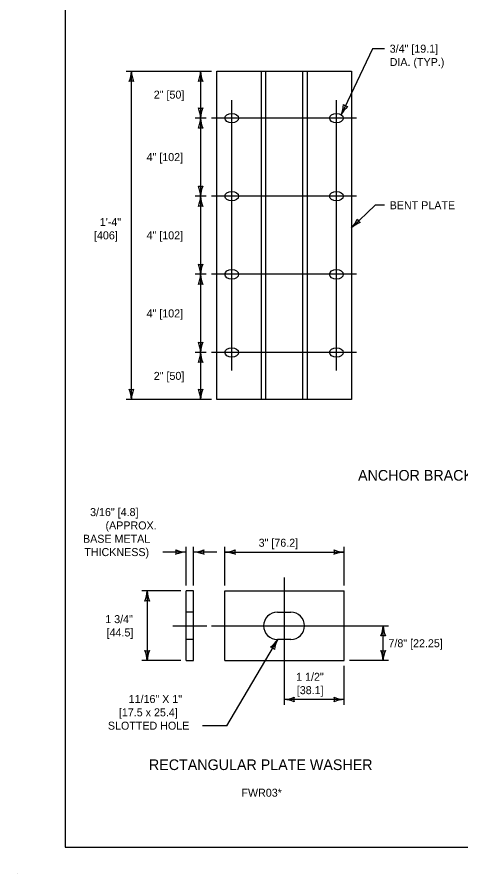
# Model space of a CAD drawing. Extents: x 49991.4 to 50021, y 49987.6 to 50011.4.
# Drawn here: x 49999.98 to 50003.3, y 49999.86 to 50006.29 of the extents above; entities that cross this region are included whole.
import ezdxf

# ---------------------------------------------------------------- set-up
doc = ezdxf.new("R2010")
doc.units = 0
for name, color, linetype in [('Default', 7, 'Continuous'), ('Level 1', 7, 'Continuous'), ('Level 2', 7, 'Continuous'), ('Level 3', 7, 'Continuous'), ('Level 4', 7, 'Continuous'), ('Level 5', 7, 'Continuous')]:
    doc.layers.add(name, color=color, linetype=linetype)

msp = doc.modelspace()

# ---------------------------------------------------------------- linework, layer by layer
at = {"layer": 'Default'}
msp.add_line((50000.3356, 50000.0624), (50000.5106, 50000.0624), dxfattribs=at)
at = {"layer": 'Level 1'}
for p, q in [((50001.4729, 50005.8814), (50002.4837, 50005.8814)), ((50001.4729, 50003.4206), (50001.4729, 50005.8814)), ((50001.8065, 50005.8814), (50001.8065, 50003.4206)), ((50002.1515, 50005.8814), (50002.1515, 50003.4206)), ((50002.4837, 50005.8814), (50002.4837, 50003.4206)), ((50002.4837, 50003.4206), (50001.4729, 50003.4206)), ((50001.2429, 50001.4614), (50001.2429, 50001.984)), ((50001.2993, 50001.984), (50001.2429, 50001.984)), ((50001.2993, 50001.4614), (50001.2993, 50001.984)), ((50001.5343, 50001.4614), (50001.5343, 50001.984)), ((50001.5343, 50001.984), (50002.4292, 50001.984)), ((50002.4292, 50001.4614), (50002.4292, 50001.984)), ((50001.9277, 50001.8256), (50002.0289, 50001.8256)), ((50002.0289, 50001.6196), (50001.9277, 50001.6196)), ((50001.2429, 50001.4614), (50001.2993, 50001.4614)), ((50001.5343, 50001.4614), (50002.4292, 50001.4614)), ((49999.9766, 49999.8624), (49999.9766, 49999.8624))]:
    msp.add_line(p, q, dxfattribs=at)
msp.add_lwpolyline([(50008.6146, 50011.2628), (50000.3356, 50011.2628), (50000.3356, 50000.0624), (50008.6146, 50000.0624)], close=True, dxfattribs=at)
for centre, start, end in [((50001.9277, 50001.7226), 90, 270), ((50002.0289, 50001.7226), 270, 90)]:
    msp.add_arc(centre, 0.103, start, end, dxfattribs=at)
for centre, major_axis in [((50001.5861, 50005.5297), (-0.0512, 0)), ((50002.3705, 50005.5297), (0.0512, 0)), ((50001.5861, 50004.9444), (-0.0512, 0)), ((50002.3705, 50004.9444), (0.0512, 0)), ((50001.5861, 50004.3585), (-0.0512, 0)), ((50002.3705, 50004.3585), (0.0512, 0)), ((50001.5861, 50003.7726), (-0.0512, 0)), ((50002.3705, 50003.7726), (0.0512, 0))]:
    msp.add_ellipse(centre, major_axis=major_axis, ratio=0.697594, dxfattribs=at)
at = {"layer": 'Level 3'}
for p, q in [((50002.6409, 50006.0504), (50002.406, 50005.5554)), ((50002.7299, 50006.0504), (50002.6409, 50006.0504)), ((50001.4329, 50005.8806), (50000.7932, 50005.8806)), ((50000.8332, 50003.4208), (50000.8332, 50005.8806)), ((50001.3521, 50005.8806), (50001.3521, 50005.5297)), ((50001.395, 50005.5297), (50001.3121, 50005.5297)), ((50001.3521, 50005.5297), (50001.3521, 50004.9443)), ((50001.395, 50004.9444), (50001.3121, 50004.9444)), ((50001.3521, 50004.9444), (50001.3521, 50004.3582)), ((50002.6615, 50004.8762), (50002.4837, 50004.706)), ((50002.7299, 50004.8762), (50002.6615, 50004.8762)), ((50001.395, 50004.3585), (50001.3121, 50004.3585)), ((50001.3521, 50004.3582), (50001.3521, 50003.7726)), ((50001.395, 50003.7726), (50001.3121, 50003.7726)), ((50001.3521, 50003.7726), (50001.3521, 50003.4208)), ((50001.4329, 50003.4208), (50000.7932, 50003.4208)), ((50001.2429, 50002.2754), (50001.0695, 50002.2754)), ((50001.2429, 50002.024), (50001.2429, 50002.3154)), ((50001.2993, 50002.024), (50001.2993, 50002.3154)), ((50001.4727, 50002.2754), (50001.2993, 50002.2754)), ((50001.5343, 50002.024), (50001.5343, 50002.3154)), ((50001.5343, 50002.2754), (50002.4292, 50002.2754)), ((50002.4292, 50002.024), (50002.4292, 50002.3154)), ((50001.2029, 50001.984), (50000.9115, 50001.984)), ((50000.9515, 50001.984), (50000.9515, 50001.4614)), ((50002.7206, 50001.4614), (50002.7206, 50001.7226)), ((50001.5497, 50000.9736), (50001.9302, 50001.6196)), ((50001.2029, 50001.4614), (50000.9115, 50001.4614)), ((50002.7606, 50001.4614), (50002.4692, 50001.4614)), ((50002.4292, 50001.13), (50002.4292, 50001.4214)), ((50002.4292, 50001.17), (50001.9783, 50001.17)), ((50001.5497, 50000.9736), (50001.3656, 50000.9736))]:
    msp.add_line(p, q, dxfattribs=at)
for centre, radius, start, end in [((50000.6111, 50005.8898), 0.2223, 337.45601, 357.63952), ((50001.0659, 50005.8921), 0.233, 182.82731, 202.07716), ((50001.13, 50005.8898), 0.2223, 337.45601, 357.63952), ((50001.5848, 50005.8921), 0.233, 182.82731, 202.07716), ((50000.8332, 50005.7524), 0.0548, 72.13882, 107.86118), ((50001.3521, 50005.7524), 0.0548, 72.13882, 107.86118), ((50002.2014, 50005.6423), 0.2223, 336.97767, 357.16118), ((50002.6113, 50005.4452), 0.233, 132.54003, 151.78988), ((50002.461, 50005.6712), 0.0548, 226.75601, 262.47837), ((50001.3521, 50005.6579), 0.0548, 252.13882, 287.86118), ((50001.1194, 50005.5182), 0.233, 2.82731, 22.07716), ((50001.5742, 50005.5205), 0.2223, 157.45601, 177.63952), ((50001.13, 50005.5389), 0.2223, 337.45601, 357.63952), ((50001.5848, 50005.5412), 0.233, 182.82731, 202.07716), ((50001.3521, 50005.4015), 0.0548, 72.13882, 107.86118), ((50001.3521, 50005.0726), 0.0548, 252.13882, 287.86118), ((50001.1194, 50004.9329), 0.233, 2.82731, 22.07716), ((50001.5742, 50004.9352), 0.2223, 157.45601, 177.63952), ((50001.13, 50004.9535), 0.2223, 337.45601, 357.63952), ((50001.5848, 50004.9558), 0.233, 182.82731, 202.07716), ((50001.3521, 50004.8161), 0.0548, 72.13882, 107.86118), ((50002.3125, 50004.864), 0.233, 317.29211, 336.54196), ((50002.6328, 50004.5411), 0.2223, 111.92081, 132.10432), ((50002.5752, 50004.7958), 0.0548, 206.60362, 242.32598), ((50001.3521, 50004.4867), 0.0548, 252.13882, 287.86118), ((50001.1194, 50004.347), 0.233, 2.82731, 22.07716), ((50001.5742, 50004.3493), 0.2223, 157.45601, 177.63952), ((50001.13, 50004.3676), 0.2223, 337.45601, 357.63952), ((50001.5848, 50004.37), 0.233, 182.82731, 202.07716), ((50001.3521, 50004.2303), 0.0548, 72.13882, 107.86118), ((50001.3521, 50003.9008), 0.0548, 252.13882, 287.86118), ((50001.1194, 50003.7611), 0.233, 2.82731, 22.07716), ((50001.5742, 50003.7634), 0.2223, 157.45601, 177.63952), ((50001.13, 50003.7818), 0.2223, 337.45601, 357.63952), ((50001.5848, 50003.7841), 0.233, 182.82731, 202.07716), ((50001.3521, 50003.6444), 0.0548, 72.13882, 107.86118), ((50000.8332, 50003.549), 0.0548, 252.13882, 287.86118), ((50000.6005, 50003.4093), 0.233, 2.82731, 22.07716), ((50001.0553, 50003.4116), 0.2223, 157.45601, 177.63952), ((50001.3521, 50003.549), 0.0548, 252.13882, 287.86118), ((50001.1194, 50003.4093), 0.233, 2.82731, 22.07716), ((50001.5742, 50003.4116), 0.2223, 157.45601, 177.63952), ((50001.2521, 50002.4976), 0.2223, 247.45601, 267.63952), ((50001.1147, 50002.2754), 0.0548, 342.13882, 17.86118), ((50001.2544, 50002.0427), 0.233, 92.82731, 112.07716), ((50001.2878, 50002.5081), 0.233, 272.82731, 292.07716), ((50001.2901, 50002.0533), 0.2223, 67.45601, 87.63952), ((50001.4275, 50002.2754), 0.0548, 162.13882, 197.86118), ((50001.5228, 50002.5081), 0.233, 272.82731, 292.07716), ((50001.5251, 50002.0533), 0.2223, 67.45601, 87.63952), ((50001.6625, 50002.2754), 0.0548, 162.13882, 197.86118), ((50002.4383, 50002.4976), 0.2223, 247.45601, 267.63952), ((50002.3009, 50002.2754), 0.0548, 342.13882, 17.86118), ((50002.4406, 50002.0427), 0.233, 92.82731, 112.07716), ((50000.7294, 50001.9932), 0.2223, 337.45601, 357.63952), ((50001.1842, 50001.9955), 0.233, 182.82731, 202.07716), ((50000.9515, 50001.8558), 0.0548, 72.13882, 107.86118), ((50002.4984, 50001.7317), 0.2223, 337.45601, 357.63952), ((50002.9533, 50001.7341), 0.233, 182.82731, 202.07716), ((50002.7206, 50001.5944), 0.0548, 72.13882, 107.86118), ((50001.7356, 50001.7476), 0.233, 307.41961, 326.66946), ((50001.8652, 50001.5091), 0.0548, 41.63559, 77.35796), ((50002.1263, 50001.5147), 0.2223, 151.85726, 172.04076), ((50000.9515, 50001.5896), 0.0548, 252.13882, 287.86118), ((50000.7188, 50001.4499), 0.233, 2.82731, 22.07716), ((50001.1736, 50001.4523), 0.2223, 157.45601, 177.63952), ((50002.7206, 50001.5896), 0.0548, 252.13882, 287.86118), ((50002.4878, 50001.4499), 0.233, 2.82731, 22.07716), ((50002.9427, 50001.4523), 0.2223, 157.45601, 177.63952), ((50001.9668, 50001.4027), 0.233, 272.82731, 292.07716), ((50002.1065, 50001.17), 0.0548, 162.13882, 197.86118), ((50002.4383, 50001.3922), 0.2223, 247.45601, 267.63952), ((50002.3009, 50001.17), 0.0548, 342.13882, 17.86118), ((50001.9691, 50000.9479), 0.2223, 67.45601, 87.63952), ((50002.4406, 50000.9373), 0.233, 92.82731, 112.07716)]:
    msp.add_arc(centre, radius, start, end, dxfattribs=at)
at = {"layer": 'Level 4'}
for p, q in [((50001.8397, 50005.8814), (50001.8397, 50003.4206)), ((50002.1169, 50005.8814), (50002.1169, 50003.4206)), ((50001.2993, 50001.8256), (50001.2429, 50001.8256)), ((50001.2993, 50001.6196), (50001.2429, 50001.6196))]:
    msp.add_line(p, q, dxfattribs=at)
at = {"layer": 'Level 5'}
for p, q in [((50001.5861, 50003.6369), (50001.5861, 50005.6654)), ((50002.3705, 50003.6369), (50002.3705, 50005.6654)), ((50002.5216, 50005.5297), (50001.435, 50005.5297)), ((50002.5216, 50004.9444), (50001.435, 50004.9444)), ((50002.5216, 50004.3585), (50001.435, 50004.3585)), ((50002.5216, 50003.7726), (50001.435, 50003.7726)), ((50001.9783, 50002.084), (50001.9783, 50001.13)), ((50001.1429, 50001.7226), (50001.3993, 50001.7226)), ((50001.4343, 50001.7226), (50002.7606, 50001.7226))]:
    msp.add_line(p, q, dxfattribs=at)

# ---------------------------------------------------------------- texts
at = {"layer": 'Level 2'}
for s, height, p in [('3/4" [19.1]', 0.06, (50002.7699, 50006.0204)), ('DIA. (TYP.)', 0.06, (50002.7699, 50005.9204)), ('2" [50]', 0.06, (50001.001, 50005.6758)), ('4" [102]', 0.06, (50000.9471, 50005.2075)), ('BENT PLATE', 0.06, (50002.7699, 50004.8462)), ('1\'-4"', 0.06, (50000.5963, 50004.7207)), ('[406]', 0.06, (50000.5528, 50004.6207)), ('4" [102]', 0.06, (50000.9471, 50004.6211)), ('4" [102]', 0.06, (50000.9471, 50004.0354)), ('2" [50]', 0.06, (50001.001, 50003.5667)), ('ANCHOR BRACKET & END PLATE', 0.08, (50002.5328, 50002.8111)), (' 3/16" [4.8]', 0.06, (50000.5013, 50002.5454)), ('(APPROX.', 0.06, (50000.6392, 50002.4454)), ('BASE METAL', 0.06, (50000.4705, 50002.3454)), ('3" [76.2]', 0.06, (50001.7874, 50002.3154)), ('THICKNESS)', 0.06, (50000.4803, 50002.2454)), ('1 3/4"', 0.06, (50000.6374, 50001.7427)), ('[44.5]', 0.06, (50000.6474, 50001.6427)), ('7/8" [22.25]', 0.06, (50002.7606, 50001.562)), ('1 1/2"', 0.06, (50002.0684, 50001.31)), ('[38.1]', 0.06, (50002.0734, 50001.21)), ('11/16" X 1"', 0.06, (50000.8129, 50001.1436)), ('[17.5 x 25.4]', 0.06, (50000.7395, 50001.0436)), ('SLOTTED HOLE', 0.06, (50000.6571, 50000.9436)), ('RECTANGULAR PLATE WASHER', 0.08, (50000.9649, 50000.6409)), ('FWR03*', 0.06, (50001.6584, 50000.4409))]:
    msp.add_text(s, height=height, dxfattribs=at).set_placement(p)

doc.saveas('drawing.dxf')
